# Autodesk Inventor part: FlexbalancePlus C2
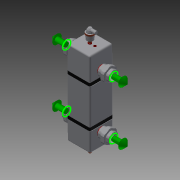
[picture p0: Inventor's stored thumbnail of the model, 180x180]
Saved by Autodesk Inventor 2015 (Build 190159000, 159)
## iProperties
allow_slope_adjustment: 0 ul
connection_type: 13 ul
flow_configuration2: 1 ul
flow_direction: 2 ul
loss_method: 0 ul
radius: 28,500 mm
Created: 2015-10
Part Number: FlexbalancePlus C2
Material: Generic
Document SubType Name: Modeling
Designer: edwin
Density: 1 g/cm^3
Appearance: Default
description: 0:0:28380_Flexbalance Ecoplus C2
manufacturer: 0:0:Flamco Group
model: 0:0:Flexbalance
url: 0:0:http://www.flamcogroup.com
Author: edwin
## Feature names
1. Revolution1
2. Extrusion1
3. Circular Pattern1
4. Revolution2
5. Extrusion2
6. Fillet1
7. Revolution3
8. Sweep1
9. Extrusion3
10. Extrusion4
11. Extrusion5
12. Rectangular Pattern1
13. Revolution4
14. Extrusion6
15. Circular Pattern2
16. Extrusion7
17. Circular Pattern3
18. Extrusion21
19. Circular Pattern10
20. Extrusion9
21. Rectangular Pattern2
22. Revolution5
23. Extrusion10
24. Circular Pattern5
25. Extrusion11
26. Circular Pattern6
27. Extrusion20
28. Circular Pattern9
29. Extrusion13
30. Rectangular Pattern3
31. Revolution6
32. Extrusion14
33. Circular Pattern8
34. Extrusion15
35. Fillet2
36. Extrusion16
37. Fillet3
38. Extrusion17
39. Extrusion18
40. Extrusion19
## Parameters: d0 = 90 deg, d2 = 14 mm, d3 = 0, d5 = 360 deg, d7 = 90 deg, d8 = 42 mm, d10 = 21 mm, d12 = 0, d13 = 1.5 mm, d14 = 90 deg, d15 = 15 mm, d16 = 292.5 mm, d17 = 0, d18 = 0, d20 = 0, d22 = 0, d23 = 2.5 mm, d25 = 0, d28 = 268 mm, d29 = 90 deg, d33 = 0, d35 = 360 deg, d38 = 0, d40 = 360 deg, d47 = 57 mm, d49 = 0, d53 = 90 deg, d57 = 0, d59 = 360 deg, d62 = 0, d64 = 360 deg, d71 = 57 mm, d73 = 0, d76 = 373 mm, d77 = 90 deg, d80 = 6 mm, d81 = 0, d83 = 360 deg, d85 = 11.5 mm, d87 = 0, d88 = 1.5 mm, d89 = 15.5 mm, d91 = 0, d92 = 1 mm, d93 = 16.6 mm, d94 = 3.5 mm, d95 = 0, d96 = 9 mm, d97 = 0, d98 = 3 mm, d99 = 0, d102 = 26 mm, d103 = 0, d105 = 360 deg, d107 = 26 mm, d108 = 0, d110 = 360 deg
